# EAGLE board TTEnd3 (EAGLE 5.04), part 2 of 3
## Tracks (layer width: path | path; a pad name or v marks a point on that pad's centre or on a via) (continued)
MASSE  (via drill 0.9 pad 1.5) (continued)
  Oben/V2 2.159: 153.42,152.15 153.42,157.48 153.42,158.75 | 155.96,152.15 155.96,157.48 R318.2 161.04,157.48 161.04,166.37 158.5,168.91 157.23,168.91 | 162.31,147.32 165.61,147.32 | 159.26,147.32 158.5,147.32 158.5,148.08 158.25,148.34 158.25,149.86 155.96,152.15 | 134.37,147.32 131.07,147.32 | 138.18,147.32 136.91,147.32 | 153.42,152.15 153.42,153.42 | 51.82,147.32 53.09,147.32 | 55.63,147.32 58.93,147.32 | 140.72,149.86 143.01,152.15 153.42,152.15 | 153.42,152.15 154.69,152.15 155.96,152.15 | 152.15,208.28 C305.2 | 147.07,208.28 C308.1 | 37.85,208.28 C105.2 | 42.93,208.28 C108.1 | 27.69,147.32 25.15,147.32 | 31.5,147.32 30.23,147.32 | 37.85,160.02 36.58,160.02 | 36.58,160.02 35.31,158.75 | 36.58,158.75 36.58,157.48 | 36.58,157.48 36.58,153.67 | 36.58,149.86 36.58,153.67 | 36.58,158.75 35.31,158.75 | 35.31,158.75 34.04,158.75 | 34.04,158.75 34.04,157.48 | 34.04,157.48 34.04,149.86 | 35.31,158.75 35.31,149.86 | 34.04,157.48 R118.2 28.96,157.48 28.96,166.37 | 35.31,168.91 31.75,168.91 31.5,168.66 29.47,168.66 28.96,168.15 | 28.96,166.37 28.96,168.15 | 28.96,168.15 29.47,167.64 30.23,167.64 | 45.47,161.29 44.2,160.02 42.93,160.02 | 37.85,160.02 42.93,160.02 | 37.85,160.02 36.58,158.75 | 30.23,167.64 28.96,166.37 | 36.58,160.02 35.31,160.02 34.04,158.75 | G117.2 41.91,152.15 38.1,152.15 36.58,153.67 | 40.39,162.56 37.85,160.02 | 40.39,167.64 30.23,167.64 | 36.58,157.48 40.39,157.48 41.66,158.75 | 42.93,160.02 41.66,158.75 | 36.58,158.75 41.66,158.75
  Oben/V2 2.54: 154.69,157.48 155.96,157.48 | 154.69,157.48 153.42,158.75 152.15,160.02 | 154.69,152.15 154.69,157.48
  Oben/V2 2.794: C129.1 51.82,86.36 J103.2 J103.1 46.74,83.82 | G318.2 145.8,147.32 | 145.8,147.32 G317.2 | 150.88,147.32 G309.1 155.96,144.78 158.5,147.32 | 150.88,147.32 G308.1 | 145.8,147.32 138.18,147.32 | 143.26,144.78 140.72,144.78 138.18,147.32 | G118.2 44.2,147.32 | G117.2 44.2,147.32 | 44.2,147.32 51.82,147.32 | 51.82,147.32 49.28,144.78 46.74,144.78 G118.2 | G117.2 49.28,149.86 51.82,147.32 | 143.26,91.44 143.26,83.82 | C318.2 148.34,86.36 J301.1 143.26,83.82 | C330.1 138.18,86.36 J303.1 J303.2 143.26,83.82 | C316.2 143.26,116.84 C328.1 | 143.26,83.82 J301.2 | G317.2 140.72,149.86 138.18,147.32 | 148.34,149.86 MP5.1 150.88,147.32 | 150.88,147.32 158.5,147.32 | G308.1 155.96,149.86 158.5,147.32 | G317.2 G308.1 | 37.85,180.34 37.85,173.99 | 37.85,180.34 38.1,180.59 38.1,187.96 35.06,191.01 35.06,200.41 37.85,203.2 37.85,208.28 37.85,213.36 40.39,215.9 40.39,219.2 40.64,219.46 40.64,222.76 40.39,223.01 40.39,226.06 50.55,236.22 81.03,236.22 82.3,237.49 92.46,237.49 | 40.64,178.82 40.64,189.23 37.6,192.28 37.6,199.14 40.39,201.93 40.39,212.09 42.93,214.63 42.93,224.79 51.82,233.68 82.3,233.68 83.57,234.95 93.73,234.95 | 92.46,232.41 89.92,232.41 | 89.92,232.41 84.84,232.41 83.57,231.14 53.09,231.14 45.47,223.52 45.47,223.01 45.22,222.76 45.22,219.2 45.47,218.95 45.47,213.36 42.93,210.82 42.93,208.28 42.93,200.66 40.14,197.87 40.14,193.29 43.18,190.25 43.18,177.55 42.93,177.29 42.93,173.99 40.39,173.99 | 95,229.87 J2.2 | 100.08,232.41 105.16,232.41 106.43,231.14 139.45,231.14 144.53,226.06 144.53,223.27 144.78,223.01 144.78,219.2 144.53,218.95 144.53,213.36 147.07,210.82 147.07,208.28 147.07,200.66 149.86,197.87 149.86,193.04 146.56,189.74 146.56,179.32 147.07,178.82 147.07,173.99 149.61,173.99
  Oben/V2 2.794: 100.08,232.41 97.54,232.41 | 93.73,234.95 95,234.95 | 95,234.95 95,231.14 | 95,234.95 106.43,234.95 | 93.73,234.95 92.46,236.22 92.46,237.49 | 92.46,237.49 106.43,237.49 107.7,236.22 141.99,236.22 149.61,228.6 149.61,222.76 149.36,222.5 149.36,219.46 149.61,219.2 149.61,215.9 152.15,213.36 152.15,208.28 152.15,203.2 154.94,200.41 154.94,190.5 151.64,187.2 151.64,180.59 154.69,177.55 154.69,173.99 152.15,173.99 | 31.5,147.32 34.04,144.78 G109.1 41.66,144.78 G118.2 | 44.2,147.32 31.5,147.32 | 31.5,147.32 34.04,149.86 35.31,149.86 36.58,149.86 G108.1 G117.2 | 37.85,168.91 35.31,168.91 | 37.85,168.91 40.39,168.91 | 42.93,168.91 40.39,168.91 | 46.74,91.44 46.74,83.82 | 46.74,83.82 J101.2 | 46.74,83.82 J101.1 41.66,86.36 C118.2 | 37.85,173.99 35.31,173.99 35.31,177.8 37.85,180.34 | 105.16,233.68 140.72,233.68 147.07,227.33 147.07,214.63 149.61,212.09 149.61,201.93 152.4,199.14 152.4,191.77 149.1,188.47 149.1,179.58 152.15,176.53 152.15,173.99 | 149.61,173.99 152.15,173.99 | 149.61,173.99 149.61,178.82 | 147.07,168.91 149.61,168.91 | 149.61,168.91 152.15,168.91 | 153.42,168.91 152.15,168.91 | 154.69,168.91 153.42,168.91 | 149.61,168.91 149.61,173.99 | 152.15,168.91 152.15,173.99 | 154.69,168.91 157.23,168.91 | 147.07,168.91 144.53,168.91 144.53,161.29 147.07,161.29 | 147.07,161.29 147.07,168.91 | 149.61,165.1 149.61,168.91 | 149.61,163.83 149.61,165.1 | 149.61,161.29 149.61,163.83 | 149.61,161.29 147.07,161.29 | 149.61,165.1 153.42,168.91 | 149.61,163.83 154.69,168.91 | 147.07,161.29 150.37,157.99 152.91,157.99 | 153.42,157.48 152.91,157.99 | 152.91,157.99 149.61,161.29 | 37.85,173.99 40.39,173.99
  Oben/V2 2.794: 40.39,173.99 40.39,179.07 | 37.85,173.99 37.85,168.91 | 40.39,173.99 40.39,168.91 | 42.93,168.91 45.47,168.91 45.47,161.29 | 42.93,168.91 42.93,161.29 | 40.39,168.91 40.39,167.64 40.39,162.56 40.39,161.29 | 89.92,232.41 92.46,229.87 92.46,223.52 J2.1 97.54,223.52 97.54,229.87 100.08,232.41
  Oben/V2 3.302: C128.1 C129.1 46.74,91.44 | C127.1 C128.1 | C126.1 C127.1 | C126.1 51.82,139.7 46.74,144.78 | C327.1 C328.1 C329.1 | C329.1 C330.1 143.26,91.44 | C317.2 C318.2 143.26,91.44 | C317.2 C316.2 C315.2 | 143.26,104.14 143.26,91.44 | 143.26,104.14 143.26,116.84 143.26,129.54 | 143.26,104.14 C317.2 | C329.1 143.26,104.14 | 143.26,129.54 C315.2 | C327.1 143.26,129.54 | C315.2 148.34,139.7 153.42,144.78 G309.1 | C327.1 138.18,139.7 143.26,144.78 G318.2 | 92.46,232.41 95,229.87 97.54,232.41 | 41.66,144.78 v46.74,139.7 46.74,129.54 | 46.74,129.54 46.74,116.84 | 46.74,116.84 46.74,104.14 | 46.74,104.14 46.74,91.44 | C117.2 C118.2 46.74,91.44 | C116.2 C117.2 | C115.2 C116.2 | C115.2 41.66,139.7 37.85,143.51 G109.1 | 46.74,129.54 C115.2 | 46.74,129.54 C126.1 | 46.74,116.84 C116.2 | 46.74,116.84 C127.1 | 46.74,104.14 C117.2 | 46.74,104.14 C128.1 | 91.19,218.95 95,222.76 J2.1 J2.2 | 143.26,129.54 v143.26,139.7 148.34,144.78 MP5.1 | 92.46,223.52 91.19,222.25 91.19,218.95 | 91.19,218.95 91.19,210.82 92.46,209.55 95,209.55
  Unten/V1 1.016: 72.14,26.67 IC105.3 | IC104.3 R199.1 | 135.64,177.8 C311.1 R330.1 | 163.58,154.94 166.12,157.48 | C111.1 56.9,181.61 58.17,182.88 59.44,182.88 R130.1 | 26.42,154.94 23.88,157.48 | IC101.2 18.8,172.72 | C319.1 150.88,35.56 R371.2 | 171.2,175.26 173.74,177.8 | IC301.2 171.2,170.18 | C132.2 95,182.88 C332.2
  Unten/V1 1.524: G137.1 R233.2 77.22,13.97 75.95,12.7 68.33,12.7 65.79,15.24 56.9,15.24 | 46.74,83.82 46.74,40.64 | R195.1 53.09,33.02 51.82,34.29 51.82,39.37 50.55,40.64 46.74,40.64 | 46.74,40.64 42.93,40.64 41.66,39.37 R177.1 C119.1 R169.2 | R189.1 MP13.1 | R189.1 MP13.1 | C120.2 IC103.2 | 46.74,40.64 R189.1 | 131.07,147.32 C314.1 | 135.64,177.8 135.64,173.99 136.91,172.72 139.45,172.72 140.72,173.99 143.26,173.99 144.53,172.72 144.53,170.18 140.72,166.37 140.72,165.1 | 140.72,165.1 V311.1 C310.1 G317.2 | 140.72,165.1 R323.1 | 166.12,157.48 166.12,163.83 168.66,166.37 IC301.2 | 163.58,154.94 C307.2 161.04,153.67 159.77,152.4 155.96,152.4 | R314.2 C301.2 R305.2 173.74,177.8 | 165.61,147.32 C304.2 | 58.93,147.32 C114.1 | 23.88,157.48 IC101.2 | 26.42,154.94 C107.2 28.96,153.67 32.77,149.86 | R114.2 C101.2 R105.2 18.8,172.72 | 24.39,147.32 C104.2 | G117.2 C110.1 V111.1 R123.1 49.28,168.91 51.82,171.45 51.82,173.99 54.36,176.53 54.36,179.07 55.63,180.34 C111.1 | 42.93,173.99 C109.1 | 35.31,173.99 C106.2 | 143.26,83.82 143.26,53.34 145.8,50.8 145.8,46.99 143.26,44.45 143.26,40.64 | C319.1 R377.1 148.34,39.37 147.07,40.64 143.26,40.64 | 143.26,40.64 138.18,40.64 135.64,38.1 R393.1 | 124.21,17.78 124.21,16.51 125.48,15.24 133.1,15.24 | 124.21,17.78 124.21,22.86 | 124.21,22.86 130.56,22.86 | 143.26,40.64 R389.1 | R389.1 MP14.1 | R376.2 158.5,15.24 IC303.2 153.42,13.97 152.15,12.7 C320.2 148.34,10.16 145.8,10.16 | 124.21,22.86 119.38,22.86 115.32,26.92 IC305.3 | J107.4 J107.3 J107.2 J107.5 84.84,2.54 82.3,5.08 45.47,5.08 44.2,6.35 R190.2 44.2,10.16 | J307.5 J307.2 J307.3 J307.4 105.16,2.54 107.7,5.08 144.53,5.08 145.8,6.35 R390.2 145.8,10.16
  Unten/V1 1.524: 95,203.2 95,208.28 G320.1 G120.1 | 95,203.2 95,200.66 | 34.04,157.48 R118.2 | 95,200.66 95,193.04 | 95,187.96 95,193.04 | v95,162.56 95,182.88 95,187.96 | 41.66,144.78 MP3.1 | 148.34,144.78 MP5.1 | R430.2 G337.1 124.21,17.78 | J101.1 36.58,81.28 v36.58,71.12 | R165.2 R166.2 | R227.1 R226.1 68.33,48.26 69.6,49.53 v69.6,63.5 | v56.9,71.12 56.9,81.28 J103.2 | R184.1 R183.1 44.2,53.34 C121.1 | R189.1 MP13.1 | R176.2 34.04,12.7 C120.2 | R199.1 70.87,25.4 72.14,26.67 | 103.89,145.54 103.89,144.78 J306.1 | R384.1 R383.1 138.18,53.34 139.45,54.61 C321.1 | R389.1 MP14.1 | R366.2 R365.2 164.85,48.26 166.12,49.53 v166.12,63.5 | J301.1 153.42,81.28 v153.42,71.12 | R426.1 R427.1 | 91.19,144.78 J106.1 | v133.1,63.5 133.1,81.28 J303.1 | 171.2,170.18 171.2,175.26 | 145.8,10.16 144.53,10.16 143.26,11.43 R389.1 | 44.2,10.16 45.47,10.16 46.74,11.43 R189.1 | 44.2,10.16 41.66,10.16 C120.2 | 56.9,15.24 IC104.3 | 95,187.96 G122.1 | 95,193.04 V119.3 | 95,203.2 V116.3 | 95,200.66 R136.2 | 95,187.96 G322.1 | 95,187.96 95,190.5 V319.3 | 95,200.66 R336.2 | 95,203.2 V316.3 | MP13.1 54.36,12.7 56.9,15.24 | MP14.1 135.64,12.7 133.1,15.24 | 130.56,22.86 R401.1 | 130.56,22.86 133.1,22.86 | 133.1,15.24 IC304.3
  Unten/V1 1.778: 136.91,147.32 134.37,147.32 | 159.77,147.32 162.31,147.32 | 30.23,147.32 27.69,147.32 | 51.82,147.32 55.63,147.32 | 147.07,172.72 C309.1 147.07,168.91 | 154.69,172.72 C306.2 154.69,168.91 | C106.2 35.31,168.91 | 42.93,168.91 C109.1
  Unten/V1 2.159: 144.53,160.02 143.26,158.75 143.26,154.69 | 143.26,154.69 143.26,153.67 144.53,152.4 148.34,152.4 | 150.88,147.32 G308.1 | 153.42,152.4 154.69,152.4 | 148.34,152.4 153.42,152.4 | 143.26,147.32 138.18,147.32 136.91,147.32 | 134.37,147.32 131.07,147.32 | 158.5,147.32 159.77,147.32 | 162.31,147.32 165.61,147.32 | 153.42,158.75 153.42,160.02 | 153.42,152.4 153.42,157.48 | 153.42,157.48 153.42,158.75 | 27.69,147.32 24.39,147.32 | 31.5,147.32 30.23,147.32 | 55.63,147.32 58.93,147.32 | 41.66,154.94 41.66,152.4 | 41.66,157.48 41.66,154.94 | 41.66,158.75 41.66,157.48 | 41.66,158.75 41.66,160.02 37.85,160.02 | 36.58,152.4 41.66,152.4 | 34.04,149.86 34.04,157.48 34.04,158.75 35.31,160.02 | 37.85,160.02 35.31,160.02 | 37.85,160.02 36.58,158.75 | 36.58,157.48 36.58,152.4 | 36.58,158.75 36.58,157.48 | 41.66,152.4 G117.2 | 36.58,149.86 36.58,152.4 | 35.31,160.02 35.31,149.86 | 153.42,158.75 152.15,160.02 | 149.61,160.02 152.15,160.02 | 148.34,160.02 149.61,160.02 | 148.34,160.02 144.53,160.02 | C105.2 37.85,208.28 | C108.1 42.93,208.28 | 96.27,229.87 J2.2 93.73,229.87 91.19,232.41 | C308.1 147.07,208.28 | C305.2 152.15,208.28 | 155.96,157.48 R318.2 | 158.25,147.57 158.25,151.38 155.96,153.67 | 152.15,160.02 149.61,162.56 | 144.53,160.02 144.53,161.29 | 41.66,157.48 36.58,157.48 | 36.58,158.75 41.66,158.75 | 45.47,161.29 45.47,160.02 46.74,158.75 46.74,156.21 45.47,154.94 | 45.47,154.94 42.93,152.4 41.66,152.4 | 40.39,162.56 37.85,160.02 | 41.66,154.94 45.47,154.94 | 44.2,161.29 41.66,158.75 | 153.42,157.48 152.15,157.48 | 152.15,157.48 149.61,160.02 | 148.34,154.69 148.34,157.48 | 148.34,157.48 148.34,160.02 | 148.34,152.4 148.34,154.69 | 148.34,154.69 143.26,154.69
  Unten/V1 2.159: 148.34,157.48 152.15,157.48
  Unten/V1 2.54: 154.69,160.02 153.42,160.02 | 154.69,160.02 155.96,158.75 155.96,157.48 155.71,157.23 155.71,154.69 | G308.1 155.71,154.69 | 154.69,152.4 154.69,160.02 | 155.71,154.69 155.71,152.65 155.96,152.4 | 42.93,210.82 45.47,213.36 45.47,219.2 arc-90 45.22,219.46 45.22,222.5 arc90 45.47,222.76 45.47,223.52 | 37.85,208.28 37.85,213.36 40.39,215.9 | 103.89,145.54 103.89,146.05 107.7,149.86 T2.11 107.7,157.48 102.62,162.56 v95,162.56 89.92,157.48 T1.11 91.19,153.67 91.19,144.78
  Unten/V1 2.794: C129.1 51.82,86.36 J103.2 J103.1 J101.2 | C118.2 41.66,86.36 J101.1 J101.2 | 46.74,83.82 J101.2 | 150.88,147.32 G309.1 148.34,144.78 G318.2 | 150.88,147.32 158.5,147.32 | 153.42,144.78 155.96,144.78 158.5,147.32 | 150.88,147.32 143.26,147.32 | 150.88,147.32 153.42,147.32 | G108.1 39.12,147.32 | 39.12,147.32 G109.1 41.66,144.78 | 36.58,144.78 34.04,144.78 31.5,147.32 | 51.82,147.32 49.28,144.78 46.74,144.78 G118.2 | G117.2 44.2,147.32 | G118.2 44.2,147.32 | G108.1 36.58,149.86 35.31,149.86 34.04,149.86 32.77,149.86 32.77,148.59 31.5,147.32 | 44.2,147.32 51.82,147.32 | 39.12,147.32 31.5,147.32 | C330.1 138.18,86.36 J303.1 J303.2 143.26,83.82 | C318.2 148.34,86.36 J301.1 143.26,83.82 | 143.26,83.82 J301.2 | 143.26,144.78 G318.2 | 41.66,144.78 G118.2 | 41.66,152.4 41.66,144.78 | G108.1 G117.2 | 51.82,147.32 49.28,149.86 G117.2 | G317.2 148.34,149.86 | 148.34,149.86 G308.1 155.96,149.86 | G317.2 140.72,149.86 | 140.72,149.86 138.18,147.32 140.72,144.78 G318.2 | G318.2 G317.2 | 158.5,147.32 158.25,147.57 155.96,149.86 | 148.34,149.86 148.34,152.4 143.26,152.4 140.72,149.86 | 155.96,149.86 155.96,152.4 | 42.93,210.82 42.93,208.28 42.93,200.66 40.14,197.87 40.14,193.29 43.18,190.25 43.18,174.24 42.93,173.99 40.39,173.99 | 40.39,215.9 40.39,218.95 40.64,219.2 40.64,222.76 40.39,223.01 40.39,226.06 50.55,236.22 53.09,236.22 | 93.73,229.87 93.73,232.41 | 93.73,232.41 92.46,233.68 v93.73,233.68 53.09,233.68 | 53.09,231.14 45.47,223.52 | 53.09,236.22 53.09,233.68 | 53.09,233.68 53.09,231.14 | 53.09,236.22 v93.73,236.22 96.27,233.68 96.27,229.87 | 53.09,236.22 54.36,236.22 42.93,224.79 42.93,214.63 40.39,212.09 40.39,201.93 37.6,199.14 37.6,192.02 40.64,188.98 40.64,174.24 40.39,173.99
  Unten/V1 2.794: 53.09,231.14 83.57,231.14 84.84,232.41 91.19,232.41 93.73,232.41 | 144.53,233.68 149.61,228.6 149.61,222.76 arc90 149.36,222.5 149.36,219.46 arc-90 149.61,219.2 149.61,215.9 152.15,213.36 152.15,208.28 149.61,208.28 | 140.72,233.68 v107.7,233.68 | 140.72,233.68 144.53,233.68 | v107.7,233.68 v107.7,231.14 139.45,231.14 144.53,226.06 144.53,223.01 arc90 144.78,222.76 144.78,219.2 arc90 144.53,218.95 144.53,213.36 147.07,210.82 147.07,208.28 149.61,208.28 | 140.72,233.68 147.07,227.33 147.07,214.63 149.61,212.09 149.61,208.28 | v107.7,233.68 v110.24,236.22 141.99,236.22 144.53,233.68 | 144.53,165.1 148.34,168.91 149.61,168.91 | 149.61,192.79 149.86,193.04 149.86,198.12 | 152.15,179.07 151.64,179.58 151.64,187.45 152.15,187.96 | 37.85,173.99 35.31,173.99 35.31,177.8 37.85,180.34 | 40.39,173.99 37.85,173.99 | 37.85,173.99 37.85,180.34 | 37.85,180.34 38.1,180.59 38.1,187.71 35.06,190.75 35.06,200.41 37.85,203.2 37.85,208.28 | 37.85,168.91 36.58,168.91 | 36.58,168.91 35.31,168.91 | 40.39,168.91 37.85,168.91 | 40.39,168.91 42.93,168.91 | 37.85,173.99 37.85,168.91 | 40.39,173.99 40.39,168.91 | 42.93,168.91 45.47,168.91 45.47,161.29 44.2,161.29 42.93,161.29 | 42.93,168.91 42.93,161.29 | 40.39,168.91 40.39,165.1 | 40.39,165.1 40.39,162.56 40.39,161.29 42.93,161.29 | 40.39,165.1 36.58,168.91 | 149.61,168.91 152.15,168.91 | 152.15,168.91 154.69,168.91 153.42,167.64 | 152.15,173.99 154.69,173.99 | 152.15,173.99 149.61,173.99 | 149.61,173.99 147.58,173.99 | 149.61,168.91 149.61,173.99 | 152.15,168.91 152.15,173.99
  Unten/V1 3.302: C126.1 51.82,139.7 46.74,144.78 | C126.1 C127.1 | C127.1 C128.1 | C128.1 C129.1 46.74,91.44 | C117.2 C118.2 46.74,91.44 | C116.2 C117.2 | C115.2 C116.2 | 46.74,129.54 C126.1 | 46.74,129.54 C115.2 | 46.74,116.84 C116.2 | 46.74,116.84 C127.1 | 46.74,104.14 C128.1 | 46.74,104.14 C117.2 | 46.74,91.44 46.74,83.82 | 46.74,104.14 46.74,91.44 | 46.74,116.84 46.74,104.14 | 46.74,129.54 46.74,116.84 | C327.1 143.26,129.54 | 143.26,129.54 C315.2 | 143.26,116.84 C316.2 | C328.1 143.26,116.84 | C329.1 143.26,104.14 | 143.26,104.14 C317.2 | 143.26,91.44 C318.2 C317.2 | 143.26,91.44 C330.1 C329.1 | C316.2 C317.2 | C316.2 C315.2 | C328.1 C329.1 | C328.1 C327.1 | 143.26,91.44 143.26,83.82 | 143.26,104.14 143.26,91.44 | 143.26,116.84 143.26,104.14 | 143.26,116.84 143.26,129.54 | 143.26,129.54 v143.26,139.7 148.34,144.78 | C115.2 41.66,139.7 36.58,144.78 G109.1 | 143.26,144.78 138.18,139.7 C327.1 | C315.2 148.34,139.7 153.42,144.78 G309.1 | 46.74,129.54 v46.74,139.7 41.66,144.78 | 144.53,161.29 144.53,165.1 | 148.34,174.75 147.07,176.02 147.07,190.25 149.61,192.79 149.61,177.8 152.15,175.26 | 147.07,161.29 147.07,163.83 149.61,166.37 | 149.61,163.83 149.61,166.37 | 149.61,163.83 149.61,162.56 149.61,161.29 | 149.61,166.37 152.15,168.91 | 154.69,173.99 154.69,176.53 152.15,179.07 | 149.61,163.83 153.42,167.64 | 149.86,198.12 147.07,200.91 147.07,208.28 | 152.15,203.2 154.69,200.66 154.69,190.5 152.15,187.96 152.15,199.39 | 152.15,208.28 152.15,203.2 | 152.15,199.39 149.61,201.93 149.61,208.28 | 152.15,199.39 152.15,203.2
N$1
  Oben/V2 1.016: C120.1 41.66,10.16 C130.1
  Unten/V1 1.016: C130.1 R202.2
N$2
  Oben/V2 1.016: C130.2 56.9,15.24 R200.1
  Unten/V1 1.016: IC102.3 50.55,22.86 51.82,21.59 51.82,16.51 C130.2
N$3
  Oben/V2 1.016: R176.1 IC103.1
  Unten/V1 1.016: R175.2 30.23,20.32 32.77,17.78 R176.1
N$4
  Oben/V2 1.016: IC103.3 36.58,6.35 37.85,5.08 75.95,5.08 79.76,8.89 G138.1
  Unten/V1 1.016: IC103.3 36.58,20.32 | MP11.1 R174.2 R175.1 36.58,20.32 | 36.58,20.32 V128.2
N$5
  Unten/V1 1.016: V128.1 IC102.7
N$6
  Oben/V2 1.016: IC104.1 56.9,17.78 R198.1
  Unten/V1 1.016: R198.1 R199.2
N$7
  Oben/V2 1.016: R192.1 54.36,25.4 V130.2 | R198.2 59.44,24.13 60.71,22.86 65.79,22.86 67.06,21.59 | MP12.1 81.03,25.4 78.49,22.86 68.33,22.86 67.06,21.59 | 67.06,21.59 G135.2
  Unten/V1 1.016: IC104.2 V130.2 R198.2
N$8
  Unten/V1 1.016: IC102.4 50.55,25.4 53.09,22.86 V130.1
N$9
  Unten/V1 1.016: C125.1 44.2,21.59 42.93,22.86 | 42.93,22.86 IC102.6 | 42.93,22.86 44.2,24.13 R188.1 C124.1 42.93,30.48 41.66,31.75 R177.2 | R186.1 42.93,35.56 41.66,34.29 R177.2 | R177.2 C119.2
N$10
  Oben/V2 1.016: R187.1 48.01,33.02 46.74,31.75 46.74,21.59 48.01,20.32 | R190.1 46.74,15.24 | 48.01,20.32 IC102.2 | 48.01,20.32 46.74,19.05 46.74,15.24 | 46.74,15.24 C125.2
N$11
  Oben/V2 1.016: R187.2 45.47,33.02 46.74,34.29 46.74,36.83 45.47,38.1 R185.2 C122.2
N$12
  Unten/V1 1.016: V308.2 176.28,167.64 176.28,158.75 177.55,157.48 | 177.55,157.48 R310.1 | 177.55,157.48 176.28,156.21 G306.2
N$13
  Unten/V1 1.016: V128.3 39.12,25.4 39.12,26.67 37.85,27.94 R173.2
N$14
  Unten/V1 1.016: R196.1 53.09,30.48 51.82,29.21 51.82,26.67 53.09,25.4 V130.3
N$15
  Oben/V2 1.016: R170.2 35.31,35.56 34.04,34.29 34.04,31.75 32.77,30.48 R172.2
  Unten/V1 1.016: R172.2 30.23,30.48 23.88,36.83 23.88,39.37 22.61,40.64 V123.3
N$16  (via drill 0.9 pad 1.5)
  Oben/V2 1.016: v44.2,48.26 R184.2
  Unten/V1 1.016: R191.2 51.82,55.88 51.82,54.61 | 51.82,54.61 R183.2 R184.2 54.36,48.26 56.9,50.8 V129.2 | R168.2 36.58,55.88 V127.2 36.58,49.53 40.39,45.72 42.93,45.72 44.2,46.99 v44.2,48.26 | 51.82,54.61 C121.2
N$17
  Oben/V2 0.762: V126.3 26.72,35.87 26.42,35.56 28.96,33.02 R171.2
N$18
  Oben/V2 1.016: 51.82,60.96 51.82,68.58 R178.2 | R181.2 51.82,60.96 | V137.2 74.68,38.1 79.76,43.18 79.76,49.53 73.41,55.88 V136.1 69.6,58.42 60.71,58.42 59.44,57.15 | 59.44,57.15 V129.1 | 59.44,57.15 55.63,60.96 51.82,60.96
N$19
  Oben/V2 0.762: V126.2 26.42,38.1 25.15,38.1
  Oben/V2 1.016: 25.15,38.1 22.61,35.56 V123.1
  Unten/V1 1.016: R173.1 30.23,27.94 22.61,35.56 V123.1
N$20
  Oben/V2 0.762: V126.1 28.66,37.8 28.96,38.1 R169.1
N$21
  Oben/V2 0.762: V126.4 28.63,35.89 28.96,35.56 R170.1
N$22
  Oben/V2 0.762: V133.3 66.75,35.26 67.06,35.56 64.52,38.1 R193.1
N$23
  Oben/V2 1.524: 6.1,101.6 6.1,102.87 8.64,105.41 18.8,105.41 20.07,104.14 G125.2 20.07,99.06 17.53,96.52 V121.1 | 6.1,101.6 2.29,97.79 2.29,95.25 3.56,93.98 3.56,66.04 G126.1 | 6.1,101.6 V120.1
  Unten/V1 1.524: 25.15,53.34 23.88,52.07 23.88,49.53 22.61,48.26 R165.1 | 11.18,58.42 G126.1 | 11.18,58.42 22.61,58.42 23.88,57.15 23.88,54.61 25.15,53.34 | 25.15,53.34 V124.2 | G127.1 11.18,58.42
N$24
  Oben/V2 1.524: G125.1 21.34,90.17 21.34,85.34 22.86,83.82 R162.2
  Unten/V1 1.524: R162.2 26.42,81.28 V124.1
N$25
  Unten/V1 1.016: J107.1 86.11,5.08 83.57,7.62 65.79,7.62 64.52,8.89 64.52,10.16 | R202.1 64.52,10.16 | 64.52,10.16 MP7.1
N$26
  Oben/V2 1.524: R153.1 R152.1 26.42,109.22 26.42,106.68 | R154.1 R153.1 | R155.1 R154.1 | R156.1 R155.1 | R157.1 R156.1 | R158.1 R157.1 | R159.1 R158.1 | R160.1 R159.1 | R160.1 R161.1 26.42,86.36 26.42,88.9 | 26.42,104.14 26.42,106.68 | 26.42,101.6 26.42,104.14 | 26.42,99.06 26.42,101.6 | 26.42,96.52 26.42,99.06 | 26.42,93.98 26.42,96.52 | 26.42,91.44 26.42,93.98 | 26.42,88.9 26.42,91.44 | R160.1 26.42,88.9 | R159.1 26.42,91.44 | R158.1 26.42,93.98 | R157.1 26.42,96.52 | R156.1 26.42,99.06 | R155.1 26.42,101.6 | R154.1 26.42,104.14 | R153.1 26.42,106.68
  Unten/V1 1.524: R153.1 R152.1 | R154.1 R153.1 | R155.1 R154.1 | R161.1 R160.1 | R160.1 R159.1 | R159.1 R158.1 | R158.1 R157.1 | R157.1 R156.1 | R156.1 R155.1 | 22.61,91.44 22.61,88.9 R160.1 | R161.1 20.07,86.36 | R152.1 21.34,109.22 20.07,107.95 | 22.61,101.6 22.61,104.14 R154.1 | 21.34,99.06 22.61,100.33 22.61,101.6 | 21.34,96.52 21.34,99.06 | 22.61,91.44 22.61,93.98 | 21.34,96.52 21.34,93.98 | R153.1 20.07,106.68 | R155.1 22.61,101.6 | R156.1 21.34,99.06 | R157.1 21.34,96.52 | R158.1 22.61,93.98 | R159.1 22.61,91.44 | R161.1 22.61,86.36 21.34,85.09 21.34,69.85 22.61,68.58 R163.2 R164.1 | 16.26,92.71 17.53,92.71 18.8,93.98 21.34,93.98 | 22.61,93.98 21.34,93.98 | R152.1 26.42,109.22 26.42,106.68 | 26.42,104.14 26.42,106.68 | 26.42,101.6 26.42,104.14 | 26.42,99.06 26.42,101.6 | 26.42,96.52 26.42,99.06 | 26.42,93.98 26.42,96.52 | 26.42,91.44 26.42,93.98 | 26.42,88.9 26.42,91.44 | 26.42,88.9 26.42,86.36 R161.1 | R160.1 26.42,88.9 | R159.1 26.42,91.44 | R158.1 26.42,93.98 | R157.1 26.42,96.52 | R156.1 26.42,99.06 | R155.1 26.42,101.6 | R154.1 26.42,104.14 | R153.1 26.42,106.68
  Unten/V1 2.794: 6.1,95.25 6.1,96.52 V121.3 | 8.64,92.71 6.1,95.25 | 12.45,92.71 16.26,92.71 16.26,85.09 | 12.45,92.71 8.64,92.71 | 8.64,85.09 6.1,85.09 4.83,86.36 4.83,96.52 | 12.45,85.09 8.64,85.09 | 16.26,85.09 12.45,85.09 | 16.26,85.09 18.8,85.09 20.07,86.36 22.61,88.9 21.34,87.63 18.8,87.63 17.53,88.9 8.64,88.9 | 20.07,107.95 20.07,106.68 22.61,104.14 | 8.64,88.9 7.37,88.9 6.1,90.17 6.1,95.25 | 8.64,88.9 8.64,92.71 | 8.64,85.09 8.64,88.9 | 12.45,85.09 12.45,92.71
N$27
  Oben/V2 0.762: V133.2 67.06,33.02 67.06,32.51 66.3,31.75 65.79,31.75 64.52,30.48
  Oben/V2 1.016: R196.2 64.52,30.48
  Unten/V1 1.016: R196.2 63.25,30.48 64.52,31.75 64.52,34.29 70.87,40.64 V137.1
N$28
  Oben/V2 0.762: V133.1 64.83,33.33 64.52,33.02 R195.2
N$29  (via drill 3.2 pad 5.99)
  other vias: 11.18,247.65
N$30
  Oben/V2 0.762: V133.4 64.83,35.26 64.52,35.56 R194.1
N$31
  Oben/V2 1.016: R194.2 58.17,35.56 59.44,34.29 59.44,30.48 R197.1
  Unten/V1 1.016: V137.3 72.14,34.29 70.87,33.02 68.33,33.02 63.25,27.94 R197.1
N$32
  Unten/V1 1.016: V125.3 R163.1
N$33
  Unten/V1 1.016: G127.2 R166.1 23.88,45.72 26.42,48.26 V124.3 V125.1
N$34  (via drill 3.2 pad 5.99)
  other vias: 82.3,69.85
N$35
  Oben/V2 1.524: R214.1 R213.1 72.14,109.22 73.41,107.95 | R215.1 R214.1 | R216.1 R215.1 | R217.1 R216.1 | R218.1 R217.1 | R219.1 R218.1 | R220.1 R219.1 | R220.1 R221.1 R222.1 | R214.1 73.41,106.68 | R215.1 72.14,104.14 73.41,105.41 70.87,102.87 70.87,101.6 | R216.1 70.87,101.6 | R217.1 72.14,99.06 73.41,97.79 70.87,100.33 70.87,101.6 | R218.1 73.41,96.52 | R219.1 72.14,93.98 | 72.14,93.98 74.68,96.52 | R220.1 72.14,93.98
  Oben/V2 2.794: 73.41,107.95 73.41,106.68 73.41,105.41 | 73.41,96.52 73.41,97.79 75.95,97.79 77.22,96.52 74.68,96.52 73.41,96.52
  Unten/V1 1.524: R222.1 R221.1 | R221.1 R220.1 | R220.1 R219.1 | R219.1 R218.1 | R218.1 R217.1 | R217.1 R216.1 | R216.1 R215.1 | R215.1 R214.1 | R214.1 R213.1 | 73.41,97.79 72.14,99.06 | 72.14,99.06 70.87,100.33 70.87,101.6 | 70.87,101.6 70.87,104.14 R215.1 | R213.1 72.14,109.22 73.41,107.95 | R214.1 73.41,106.68 | 70.87,93.98 73.41,93.98 73.41,96.52 R218.1 | 70.87,91.44 70.87,93.98 | 70.87,91.44 70.87,88.9 R221.1 | R220.1 70.87,91.44 | R219.1 70.87,93.98 | 70.87,93.98 77.22,93.98 | R222.1 72.14,86.36 73.41,87.63 | R216.1 70.87,101.6 | R217.1 72.14,99.06 | R213.1 67.06,109.22 67.06,106.68 | 67.06,104.14 67.06,106.68 | 67.06,101.6 67.06,104.14 | 67.06,99.06 67.06,101.6 | 67.06,96.52 67.06,99.06 | 67.06,93.98 67.06,96.52 | 67.06,91.44 67.06,93.98 | 67.06,88.9 67.06,91.44 | 67.06,88.9 67.06,86.36 R222.1 | R221.1 67.06,88.9 | R220.1 67.06,91.44 | R219.1 67.06,93.98 | R218.1 67.06,96.52 | R217.1 67.06,99.06 | R216.1 67.06,101.6 | R215.1 67.06,104.14 | R214.1 67.06,106.68 | R225.2 R224.2 70.87,68.58 72.14,69.85 72.14,85.09 70.87,86.36 R222.1
  Unten/V1 2.794: 77.22,96.52 75.95,97.79 73.41,97.79 73.41,96.52 V135.3 77.22,96.52 | 70.87,104.14 73.41,106.68 73.41,107.95 | 70.87,88.9 72.14,87.63 73.41,87.63 74.68,87.63 77.22,90.17 77.22,93.98 77.22,96.52
N$36
  Oben/V2 1.524: R223.1 70.62,83.82 72.14,85.34 72.14,90.17 G130.2
  Unten/V1 1.524: R223.1 67.06,81.28 V132.1
N$37
  Oben/V2 1.524: V135.1 87.38,96.52 91.19,100.33 91.19,104.14 89.92,105.41 81.03,105.41 77.22,101.6 V134.1 | V132.2 68.33,53.34 69.6,52.07 69.6,49.53 70.87,48.26 R226.2
  Unten/V1 1.524: V135.1 87.38,96.52 87.38,63.5 G133.2 79.76,55.88 79.76,48.26 | V134.1 G130.1 | R226.2 79.76,48.26 | 79.76,48.26 G134.2
N$38
  Unten/V1 1.524: G132.1 G133.1 74.68,54.61 73.41,53.34 V136.2
N$39
  Unten/V1 1.524: G132.2 R225.1
N$40
  Unten/V1 1.016: V131.3 R224.1
N$41
  Oben/V2 1.016: V132.3 67.06,48.26 69.6,45.72 R227.2
  Oben/V2 1.524: R227.2 G134.1
  Unten/V1 1.524: V131.1 V132.3
N$42
  Unten/V1 1.016: V122.3 20.07,55.88 16.26,52.07 16.26,44.45 17.53,43.18 R167.1
N$43
  Oben/V2 1.016: R230.2 69.6,11.43 63.25,17.78 R201.2
  Unten/V1 1.016: R201.2 63.25,17.78 64.52,19.05 64.52,21.59 65.79,22.86 73.41,22.86 77.22,26.67 IC105.1 C131.2 | R230.2 R231.2
N$44
  Unten/V1 1.016: R229.1 C131.1 73.41,30.48 74.68,29.21 IC105.2
N$45
  Unten/V1 1.016: IC105.5 G137.2 R230.1
N$46
  Oben/V2 1.016: R231.1 72.14,13.97 74.68,11.43 R232.2
  Unten/V1 1.016: R231.1 IC105.6 | R232.2 R233.1
N$47
  Oben/V2 1.016: G136.1 82.3,29.21 78.49,25.4 70.87,25.4 69.6,26.67 IC105.4
  Unten/V1 1.016: G135.1 IC105.4
N$48  (via drill 3.2 pad 5.99)
  other vias: 31.5,247.65
N$49  (via drill 3.2 pad 5.99)
  other vias: 54.36,247.65
N$50
  Oben/V2 1.524: R143.2 R142.2 21.34,134.62 20.07,133.35 | R144.1 R143.2 | R145.2 R144.1 | R146.2 R145.2 | R147.1 R146.2 | R148.1 R147.1 | R148.1 R149.1 | R150.2 R149.1 | R150.2 R151.1 21.34,111.76 20.07,113.03 | R143.2 20.07,132.08 | R144.1 20.07,129.54 | R145.2 20.07,127 | R146.2 20.07,124.46 | R147.1 20.07,121.92 | R148.1 20.07,119.38 | R149.1 20.07,116.84 | R150.2 20.07,114.3
  Oben/V2 2.794: 20.07,113.03 20.07,114.3 20.07,116.84 20.07,119.38 20.07,121.92 20.07,124.46 20.07,127 20.07,129.54 20.07,132.08 20.07,133.35
  Unten/V1 1.524: R143.2 R142.2 21.34,134.62 20.07,133.35 | R144.1 R143.2 | R145.2 R144.1 | R146.2 R145.2 | R147.1 R146.2 | R148.1 R147.1 | R148.1 R149.1 | R150.2 R149.1 | R150.2 R151.1 20.07,111.76 | 16.26,129.54 16.26,132.08 | 16.26,127 16.26,129.54 | 16.26,127 16.26,124.46 20.07,124.46 R146.2 | 20.07,132.08 R143.2 | R144.1 20.07,129.54 16.26,129.54 | R145.2 20.07,127 16.26,127 | R147.1 20.07,121.92 16.26,121.92 | R148.1 20.07,119.38 16.26,119.38 | R149.1 20.07,116.84 16.26,116.84 | R150.2 20.07,114.3 16.26,114.3
  Unten/V1 2.794: 16.26,132.08 17.53,133.35 20.07,133.35 20.07,132.08 20.07,129.54 20.07,127 20.07,124.46 20.07,121.92 20.07,119.38 20.07,116.84 20.07,114.3 20.07,111.76 18.8,111.76 16.26,109.22 16.26,102.87 | 16.26,119.38 16.26,121.92 16.26,124.46 11.18,119.38 11.18,114.3 | 16.26,102.87 16.26,101.6 V120.3 | 16.26,102.87 13.72,105.41 | 11.18,114.3 11.18,107.95 13.72,105.41 | 16.26,119.38 16.26,116.84 16.26,114.3 13.72,111.76 13.72,105.41 | 11.18,114.3 16.26,119.38
N$51
  Oben/V2 1.524: R204.1 R203.1 72.14,134.62 73.41,133.35 | R205.1 R204.1 | R206.2 R205.1 | R207.1 R206.2 | R208.2 R207.1 | R209.1 R208.2 | R210.2 R209.1 | R211.2 R210.2 | R211.2 R212.2 72.14,111.76 73.41,113.03 | R204.1 73.41,132.08 | R205.1 73.41,129.54 | R206.2 73.41,127 | R207.1 73.41,124.46 | R208.2 73.41,121.92 | R209.1 73.41,119.38 | R210.2 73.41,116.84 | R211.2 73.41,114.3
  Oben/V2 2.794: 73.41,113.03 73.41,114.3 73.41,116.84 73.41,119.38 73.41,121.92 73.41,124.46 73.41,127 73.41,129.54 73.41,132.08 73.41,133.35
  Unten/V1 1.524: R204.1 R203.1 72.14,134.62 73.41,133.35 | R205.1 R204.1 | R206.2 R205.1 | R207.1 R206.2 | R208.2 R207.1 | R209.1 R208.2 | R210.2 R209.1 | R211.2 R210.2 | R211.2 R212.2 74.68,111.76 79.76,111.76 | 77.22,129.54 77.22,132.08 73.41,132.08 R204.1 | 77.22,127 77.22,129.54 | 77.22,127 77.22,124.46 73.41,124.46 R207.1 | R211.2 73.41,114.3 77.22,114.3 | R210.2 73.41,116.84 77.22,116.84 | R209.1 73.41,119.38 77.22,119.38 | R208.2 73.41,121.92 77.22,121.92 | R206.2 73.41,127 77.22,127 | R205.1 73.41,129.54 77.22,129.54
  Unten/V1 2.794: 87.38,101.6 87.38,102.87 86.11,104.14 86.11,105.41 | 86.11,105.41 81.03,105.41 74.68,111.76 73.41,113.03 73.41,114.3 73.41,116.84 73.41,119.38 73.41,121.92 73.41,124.46 73.41,127 73.41,129.54 73.41,132.08 73.41,133.35 75.95,133.35 77.22,132.08 | 77.22,119.38 77.22,121.92 77.22,124.46 88.65,113.03 88.65,107.95 | 77.22,119.38 77.22,116.84 77.22,114.3 79.76,111.76 86.11,105.41 | 87.38,101.6 88.65,102.87 88.65,107.95 | 87.38,101.6 V134.3 | 77.22,119.38 88.65,107.95
N$52  (via drill 0.9 pad 1.5)
  Oben/V2 1.016: C122.1 R185.1 | R186.2 50.55,35.56 51.82,34.29 51.82,31.75 50.55,30.48 C124.2 | R167.2 30.23,43.18 35.31,48.26 37.85,48.26 40.39,45.72 46.74,45.72 C122.1 | R229.2 69.6,38.1 R228.1 63.25,43.18 61.98,44.45 61.98,45.72 59.44,48.26 55.63,48.26 50.55,43.18 C122.1
  Oben/V2 1.524: 23.88,74.93 G128.1 | 69.6,74.93 G131.2 | J102.1 46.74,73.66 46.74,52.07 48.01,50.8 v49.28,50.8
  Oben/V2 2.54: 65.79,133.35 65.79,135.89 68.33,138.43 74.68,138.43 77.22,140.97 81.03,140.97 83.57,143.51 83.57,147.32 86.11,149.86 86.11,153.67 82.3,157.48 T1.12
  Oben/V2 2.794: 44.2,74.93 39.12,74.93 | 12.45,93.98 12.45,96.52 | 14.99,91.44 12.45,93.98 | 20.07,77.47 20.07,74.93 | 20.07,77.47 20.07,80.01 | 17.53,88.9 17.53,85.09 20.07,82.55 | 17.53,88.9 14.99,91.44 | 9.91,83.82 7.37,86.36 7.37,91.44 9.91,93.98 | 12.45,81.28 9.91,83.82 | 17.53,76.2 12.45,81.28 | 20.07,74.93 18.8,74.93 17.53,76.2 | 9.91,93.98 9.91,96.52 | 83.57,96.52 83.57,100.33 V134.2 81.03,100.33 81.03,96.52 | 81.03,93.98 81.03,96.52 | 78.49,91.44 75.95,88.9 75.95,85.09 | 78.49,91.44 81.03,93.98 | 73.41,74.93 73.41,78.74 | 73.41,78.74 73.41,82.55 | 73.41,82.55 75.95,85.09 | 73.41,74.93 74.68,74.93 75.95,76.2 | 75.95,76.2 81.03,81.28 | 81.03,81.28 83.57,83.82 | 83.57,83.82 86.11,86.36 86.11,91.44 83.57,93.98 | 83.57,93.98 83.57,96.52 | 83.57,96.52 82.3,95.25 | 44.2,74.93 J102.1 44.2,77.47 | 44.2,74.93 69.6,74.93 70.87,74.93 | 70.87,74.93 72.14,76.2 J104.1 J104.2 50.55,77.47 | 70.87,74.93 73.41,74.93 | 44.2,77.47 50.55,77.47 | 56.9,80.01 56.9,78.74 55.63,77.47 50.55,77.47 | 50.55,77.47 70.87,77.47 | 20.07,74.93 23.88,74.93 39.12,74.93 | 39.12,74.93 J102.2 37.85,77.47 | 26.42,77.47 20.07,77.47 | 37.85,77.47 26.42,77.47 | 37.85,77.47 36.58,78.74 | 36.58,78.74 36.58,80.01 | 36.58,80.01 35.31,81.28 34.04,81.28 32.77,80.01 30.23,80.01 | 20.07,80.01 20.07,82.55 | 20.07,82.55 22.61,80.01 | 22.61,80.01 25.15,80.01 | 25.15,80.01 26.42,81.28 28.96,81.28 30.23,80.01 | 17.53,76.2 17.53,88.9 | 17.53,76.2 14.99,78.74 14.99,91.44 | 12.45,81.28 12.45,93.98 | 9.91,83.82 9.91,93.98 | 56.9,80.01 58.17,81.28 59.44,81.28 60.71,80.01 63.25,80.01 64.52,81.28 65.79,81.28 67.06,81.28 68.33,80.01 70.87,80.01 73.41,82.55 | 75.95,76.2 75.95,85.09 | 75.95,76.2 78.49,78.74 78.49,91.44
  Oben/V2 2.794: 81.03,81.28 81.03,93.98 | 83.57,83.82 83.57,93.98 | 44.2,77.47 37.85,77.47 | 9.91,96.52 9.91,100.33 V120.2 12.45,100.33 12.45,96.52 | 9.91,96.52 V121.2 12.45,96.52 | 81.03,96.52 V135.2 83.57,96.52 | 36.58,78.74 34.04,78.74 32.77,77.47 26.42,77.47 | 25.15,80.01 30.23,80.01 | 20.07,80.01 22.61,80.01 | 56.9,80.01 58.17,78.74 73.41,78.74 | 36.58,80.01 56.9,80.01
  Oben/V2 3.302: 65.79,81.28 65.79,133.35
  Unten/V1 1.016: C124.2 R188.2 | R185.1 R186.2
  Unten/V1 1.524: C122.1 v49.28,50.8
  Unten/V1 2.794: 12.45,97.79 12.45,100.33 V120.2 9.91,100.33 9.91,97.79 V121.2 12.45,97.79 | 83.57,97.79 83.57,100.33 V134.2 81.03,100.33 81.03,97.79 V135.2 83.57,97.79
N$54
  Oben/V2 1.016: R399.1 130.56,16.51 131.83,15.24 C326.2
  Unten/V1 1.016: IC302.3 139.45,20.32 138.18,19.05 138.18,16.51 C326.2
N$55
  Unten/V1 1.016: R375.2 159.77,20.32 157.23,17.78 R376.1 IC303.1
N$56
  Oben/V2 1.016: IC303.3 153.42,12.7 153.42,6.35 152.15,5.08 114.05,5.08 110.24,8.89 G338.1
  Unten/V1 1.016: 155.96,22.86 R375.1 | 155.96,22.86 R374.2 MP9.1 | IC303.3 V328.2 153.42,22.86 155.96,22.86
N$57
  Oben/V2 1.016: V119.2 89.92,193.04 89.92,194.31 88.65,195.58 R138.2 V118.1
N$58
  Unten/V1 1.016: R398.1 R401.2 IC304.1
N$59
  Oben/V2 1.016: IC302.4 139.45,17.78 138.18,19.05 138.18,21.59 136.91,22.86 V330.1
N$60
  Unten/V1 1.016: C325.1 145.8,19.05 147.07,20.32 | 147.07,20.32 IC302.6 | 147.07,20.32 145.8,21.59 R388.1 C324.1 147.07,30.48 148.34,31.75 R377.2 | R377.2 148.34,34.29 147.07,35.56 R386.1 | R377.2 C319.2
N$61
  Oben/V2 1.016: 141.99,22.86 IC302.2 | R387.1 141.99,33.02 143.26,31.75 143.26,24.13 141.99,22.86 | 143.26,15.24 143.26,21.59 141.99,22.86 | 143.26,15.24 R390.1 | C325.2 143.26,15.24
N$62
  Oben/V2 1.016: R387.2 144.53,33.02 143.26,34.29 143.26,36.83 144.53,38.1 R385.2 C322.2
N$63
  Oben/V2 1.016: V328.3 R373.2
N$64
  Unten/V1 1.016: V330.3 R397.1
N$65
  Unten/V1 1.016: V323.3 164.85,35.56 159.77,30.48 R372.2 157.23,30.48 155.96,31.75 155.96,34.29 154.69,35.56 R370.2
N$66
  Oben/V2 1.016: V323.2 171.2,38.1 176.28,43.18 176.28,49.53 169.93,55.88 V322.1 166.12,58.42 159.77,58.42 155.96,54.61 | 155.96,54.61 V327.1 | 155.96,54.61 154.18,56.39 149.1,56.39 147.07,58.42 R382.1
  Unten/V1 1.016: R379.1 148.34,64.77 148.34,59.69 147.07,58.42 R382.1
N$67
  Oben/V2 0.762: R369.2 161.04,38.1 163.58,35.56 163.28,35.26 V326.3
N$68
  Oben/V2 0.762: V326.2 163.58,33.02 163.58,31.75
  Oben/V2 1.016: 163.58,31.75 159.77,27.94 R373.1
  Unten/V1 1.016: V323.1 169.93,40.64 171.2,39.37 171.2,34.29 167.39,30.48 162.31,30.48 159.77,27.94 R373.1
N$69
  Oben/V2 0.762: V326.1 161.34,33.33 161.04,33.02 R371.1
N$70
  Oben/V2 0.762: V326.4 161.34,35.26 161.04,35.56 R370.1
N$71  (via drill 3.2 pad 5.99)
  other vias: 82.3,128.27
N$72
  Unten/V1 1.016: IC302.7 V328.1
N$73
  Oben/V2 1.524: G325.1 168.66,90.17 168.66,85.34 167.14,83.82 R362.2
  Unten/V1 1.524: R362.2 163.58,81.28 V324.1
N$74
  Oben/V2 1.524: R353.1 R352.1 | R354.1 R353.1 | R355.1 R354.1 | R360.1 R361.1 163.58,86.36 163.58,88.9 | R360.1 R359.1 | R359.1 R358.1 | R358.1 R357.1 | R357.1 R356.1 | R356.1 R355.1 | R352.1 168.66,109.22 169.93,107.95 | R358.1 167.39,93.98 167.39,92.71 R359.1 | 167.39,101.6 167.39,99.06 R356.1 | 167.39,101.6 167.39,104.14 R354.1 | R353.1 169.93,106.68 | R355.1 167.39,101.6 | R357.1 169.93,96.52 | R352.1 163.58,109.22 163.58,106.68 | 163.58,104.14 163.58,106.68 | 163.58,101.6 163.58,104.14 | 163.58,99.06 163.58,101.6 | 163.58,96.52 163.58,99.06 | 163.58,93.98 163.58,96.52 | 163.58,91.44 163.58,93.98 | 163.58,88.9 163.58,91.44 | R360.1 163.58,88.9 | R359.1 163.58,91.44 | R358.1 163.58,93.98 | R357.1 163.58,96.52 | R356.1 163.58,99.06 | R355.1 163.58,101.6 | R354.1 163.58,104.14 | R353.1 163.58,106.68
  Oben/V2 2.54: 169.93,96.52 173.74,96.52
  Oben/V2 2.794: 167.39,93.98 169.93,96.52 167.39,99.06 | 167.39,104.14 169.93,106.68 169.93,107.95
  Unten/V1 1.524: 168.66,88.9 168.66,86.36 | R361.1 168.66,86.36 | R352.1 168.66,109.22 169.93,107.95 | 168.66,104.14 169.93,105.41 169.93,106.68 R353.1 | 168.66,96.52 168.66,99.06 | 167.39,91.44 167.39,93.98 | R354.1 168.66,104.14 | R355.1 167.39,101.6 | R356.1 168.66,99.06 | R357.1 168.66,96.52 | R358.1 167.39,93.98 | R359.1 167.39,91.44 | R360.1 168.66,88.9 | R353.1 R352.1 | R354.1 R353.1 | R355.1 R354.1 | R356.1 R355.1 | R357.1 R356.1 | R358.1 R357.1 | R359.1 R358.1 | R360.1 R359.1 | R360.1 R361.1 | 167.39,101.6 167.39,102.87 168.66,104.14 | 168.66,99.06 167.39,100.33 167.39,101.6 | 168.66,99.06 171.2,99.06 172.47,97.79 172.47,96.52 168.66,96.52 | 167.39,93.98 168.66,95.25 168.66,96.52 | 168.66,88.9 173.74,88.9 | 167.39,91.44 167.39,92.71 168.66,93.98 171.2,93.98 173.74,91.44 | 167.39,93.98 173.74,93.98 | R364.1 R363.2 167.39,68.58 168.66,69.85 168.66,86.36 | R352.1 163.58,109.22 163.58,106.68 | 163.58,104.14 163.58,106.68 | 163.58,101.6 163.58,104.14 | 163.58,99.06 163.58,101.6 | 163.58,96.52 163.58,99.06 | 163.58,93.98 163.58,96.52 | 163.58,91.44 163.58,93.98 | 163.58,88.9 163.58,91.44 | 163.58,88.9 163.58,86.36 R361.1 | R360.1 163.58,88.9 | R359.1 163.58,91.44 | R358.1 163.58,93.98 | R357.1 163.58,96.52 | R356.1 163.58,99.06 | R355.1 163.58,101.6 | R354.1 163.58,104.14 | R353.1 163.58,106.68 | 167.39,91.44 167.39,90.17 168.66,88.9
  Unten/V1 2.794: 169.93,106.68 169.93,107.95 | V321.3 173.74,96.52 172.47,96.52
  Unten/V1 3.302: 168.66,86.36 171.2,86.36 173.74,88.9 173.74,91.44 173.74,93.98 173.74,96.52
N$75
  Oben/V2 0.762: V333.2 122.94,33.02 R397.2
  Unten/V1 1.016: R397.2 126.75,27.94 122.94,31.75 122.94,34.29 121.67,35.56 V337.1
N$76
  Oben/V2 0.762: V333.1 123.24,35.26 122.94,35.56
  Oben/V2 1.016: R393.2 125.48,38.1 122.94,35.56
N$77
  Oben/V2 0.762: V333.3 125.17,33.33 125.48,33.02
  Oben/V2 1.016: 125.48,33.02 R395.1
N$78
  Oben/V2 0.762: V333.4 125.17,35.26 125.48,35.56
  Oben/V2 1.016: 125.48,35.56 R394.1
N$79
  Oben/V2 1.016: R396.1 129.29,30.48 130.56,31.75 130.56,34.29 131.83,35.56 R394.2
  Unten/V1 1.016: V337.3 121.67,40.64 125.48,36.83 125.48,31.75 126.75,30.48 R396.1
N$80
  Oben/V2 1.016: 138.18,68.58 R378.2 | 138.18,68.58 138.18,62.23 139.45,60.96 R381.2 | V337.2 116.59,38.1 112.78,41.91 112.78,46.99 116.59,50.8 V336.1 119.13,50.8 120.4,52.07 120.4,57.15 121.67,58.42 130.56,58.42 | 130.56,58.42 132.34,58.42 135.64,55.12 V329.1 | 130.56,58.42 130.56,64.77 134.37,68.58 138.18,68.58
N$81
  Unten/V1 1.016: R136.1 R137.2 V118.3
N$82
  Oben/V2 1.524: R422.1 R421.1 R420.1 R419.1 R418.1 R417.1 R416.1 R415.1 R414.1 R413.1
  Unten/V1 1.524: R413.1 117.86,109.22 116.59,107.95 | R414.1 116.59,106.68 | R415.1 119.13,104.14 119.13,101.6 | 119.13,91.44 119.13,92.71 117.86,93.98 | 117.86,88.9 119.13,90.17 119.13,91.44 | 117.86,86.36 117.86,88.9 | R418.1 117.86,96.52 | R419.1 117.86,93.98 | 119.13,91.44 R420.1 | 117.86,88.9 R421.1 | 117.86,86.36 R422.1 | R416.1 119.13,101.6 | R417.1 117.86,99.06 | R414.1 R413.1 | R415.1 R414.1 | R416.1 R415.1 | R417.1 R416.1 | R418.1 R417.1 | R419.1 R418.1 | R420.1 R419.1 | R421.1 R420.1 | R422.1 R421.1 | 117.86,99.06 119.13,100.33 119.13,101.6 | 117.86,93.98 117.86,96.52 | 117.86,96.52 117.86,99.06 | 117.86,93.98 115.32,93.98 114.05,92.71 112.78,92.71 | 117.86,88.9 112.78,88.9 | R413.1 122.94,109.22 122.94,106.68 | 122.94,104.14 122.94,106.68 | 122.94,101.6 122.94,104.14 | 122.94,99.06 122.94,101.6 | 122.94,96.52 122.94,99.06 | 122.94,93.98 122.94,96.52 | 122.94,91.44 122.94,93.98 | 122.94,88.9 122.94,91.44 | 122.94,88.9 122.94,86.36 R422.1 | R421.1 122.94,88.9 | R420.1 122.94,91.44 | R419.1 122.94,93.98 | R418.1 122.94,96.52 | R417.1 122.94,99.06 | R416.1 122.94,101.6 | R415.1 122.94,104.14 | R414.1 122.94,106.68 | R425.2 R424.2 119.13,68.58 117.86,69.85 117.86,86.36
  Unten/V1 2.794: 112.78,85.09 112.78,92.71 108.97,92.71 | 105.16,92.71 102.27,95.6 V335.3 102.62,96.52 102.62,90.17 103.89,88.9 112.78,88.9 | 116.59,107.95 116.59,106.68 119.13,104.14 | 108.97,92.71 105.16,92.71 | 117.86,86.36 116.59,85.09 112.78,85.09 | 105.16,85.09 102.62,85.09 101.35,86.36 101.35,96.52 | 108.97,85.09 105.16,85.09 | 112.78,85.09 108.97,85.09 | 108.97,85.09 108.97,92.71 | 105.16,85.09 105.16,92.71
N$83
  Oben/V2 1.524: G330.2 117.86,90.17 117.86,85.34 119.38,83.82 R423.1
  Unten/V1 1.524: R423.1 122.94,81.28 V332.1
N$84
  Oben/V2 1.524: V335.1 112.78,96.52 116.59,100.33 G330.1 116.59,102.87 114.05,105.41 106.43,105.41 102.62,101.6 V334.1 101.35,101.6 98.81,99.06 98.81,95.25 100.08,93.98 100.08,66.04 G333.2
  Unten/V1 1.524: 121.67,53.34 120.4,52.07 120.4,49.53 119.13,48.26 R426.2 | 107.7,58.42 G333.2 | 107.7,58.42 119.13,58.42 120.4,57.15 120.4,54.61 121.67,53.34 | 121.67,53.34 V332.2 | G334.2 107.7,58.42
N$85
  Unten/V1 1.016: J307.1 103.89,5.08 106.43,7.62 122.94,7.62 125.48,10.16 | 125.48,10.16 R402.1 | 125.48,10.16 MP8.1
N$86
  Unten/V1 1.016: V325.3 R363.1
N$87
  Oben/V2 1.016: R368.1 149.61,63.5 147.07,60.96 R381.1
  Unten/V1 1.016: R378.1 150.88,71.12 153.42,68.58 153.42,67.31 152.15,66.04 P301.1 R368.1 153.42,60.96 153.42,57.15 150.88,54.61 V327.3
N$88
  Unten/V1 1.016: R379.2 R380.2 138.18,63.5 | 138.18,63.5 R391.1 135.64,60.96 130.56,55.88 V329.3 | R382.2 139.45,58.42 138.18,59.69 138.18,63.5
N$89  (via drill 0.9 pad 1.5)
  Oben/V2 1.016: 133.1,22.86 V330.2 | R398.2 128.02,24.13 129.29,22.86 133.1,22.86 | IC304.2 133.1,20.32 133.1,22.86 | 110.24,24.13 111.51,25.4 v122.94,25.4 | MP10.1 108.97,25.4 110.24,24.13 | 110.24,24.13 G335.2
  Unten/V1 1.016: v122.94,25.4 R398.2 | V330.2 R392.1
N$90  (via drill 0.9 pad 1.5)
  Oben/V2 1.016: v143.26,48.26 R384.2
  Unten/V1 1.016: 148.34,54.61 R383.2 R384.2 150.88,48.26 153.42,50.8 V327.2 | 148.34,54.61 C321.2 | 148.34,54.61 148.34,55.88 R368.2 | R391.2 133.1,55.88 V329.2 133.1,49.53 136.91,45.72 139.45,45.72 141.99,48.26 v143.26,48.26
N$91
  Oben/V2 1.016: V324.3 163.58,48.26 166.12,45.72 R366.1
  Unten/V1 1.016: V325.1 V324.3 | R366.1 G329.2
N$92
  Unten/V1 1.524: G328.1 R364.2
N$93
  Unten/V1 1.016: R201.1 R200.2 59.44,8.89 58.17,7.62 R189.2
N$94
  Oben/V2 1.016: 126.75,17.78 125.48,19.05 125.48,26.67 124.21,27.94 IC305.1 | R432.2 115.32,11.43 116.59,12.7 121.67,12.7 126.75,17.78 | 126.75,17.78 R400.2
  Unten/V1 1.016: IC305.1 C331.2 | R433.2 R432.2
N$95
  Unten/V1 1.016: IC305.2 117.86,29.21 116.59,30.48 | 116.59,30.48 119.13,33.02 R429.1 | C331.1 116.59,30.48
N$96
  Unten/V1 1.016: IC305.5 G337.2 R433.1
N$97
  Unten/V1 1.016: IC305.6 R432.1 115.32,13.97 117.86,11.43 R431.2 R430.1
N$98
  Unten/V1 1.016: G136.2 83.57,22.86 91.19,15.24 J4.2 105.16,20.32 105.16,21.59 106.43,22.86 G336.2
N$99  (via drill 3.2 pad 5.99)
  other vias: 74.68,247.65
N$100  (via drill 3.2 pad 5.99)
  other vias: 115.32,247.65
N$101
  Oben/V2 1.524: R343.2 R342.2 168.66,134.62 169.93,133.35 | R344.1 R343.2 | R345.2 R344.1 | R346.2 R345.2 | R347.1 R346.2 | R348.1 R347.1 | R349.1 R348.1 | R350.2 R349.1 | R350.2 R351.1 168.66,111.76 169.93,113.03 | R350.2 169.93,114.3 | R349.1 169.93,116.84 | R348.1 169.93,119.38 | R347.1 169.93,121.92 | R346.2 169.93,124.46 | R345.2 169.93,127 | R344.1 169.93,129.54 | R343.2 169.93,132.08
  Oben/V2 2.794: 169.93,113.03 169.93,114.3 169.93,116.84 169.93,119.38 169.93,121.92 169.93,124.46 169.93,127 169.93,129.54 169.93,132.08 169.93,133.35
  Unten/V1 1.524: 173.74,129.54 169.93,133.35 168.66,134.62 R342.2 R343.2 | 173.74,127 173.74,129.54 | 173.74,127 173.74,124.46 169.93,124.46 R346.2 | R343.2 169.93,132.08 | R344.1 169.93,129.54 173.74,129.54 | R345.2 169.93,127 173.74,127 | R347.1 169.93,121.92 173.74,121.92 | R348.1 169.93,119.38 173.74,119.38 | R349.1 169.93,116.84 173.74,116.84 | R350.2 169.93,114.3 173.74,114.3 | 176.28,111.76 171.2,111.76 169.93,111.76 R351.1 R350.2 | R344.1 R343.2 | R345.2 R344.1 | R346.2 R345.2 | R347.1 R346.2 | R348.1 R347.1 | R349.1 R348.1 | R350.2 R349.1
  Unten/V1 2.794: 173.74,119.38 173.74,121.92 173.74,124.46 185.17,113.03 185.17,107.95 | 173.74,119.38 173.74,116.84 173.74,114.3 176.28,111.76 183.9,104.14 | 169.93,133.35 169.93,132.08 169.93,129.54 169.93,127 169.93,124.46 169.93,121.92 169.93,119.38 169.93,116.84 169.93,114.3 169.93,111.76 | 183.9,104.14 183.9,101.95 V320.3 | 185.17,107.95 185.17,102.87 183.9,104.14 | 171.2,111.76 177.55,105.41 181.36,105.41 183.9,102.87 | 173.74,119.38 185.17,107.95
N$102
  Oben/V2 1.524: R404.1 R403.1 117.86,134.62 116.59,133.35 | R404.1 R405.1 | R405.1 R406.2 | R406.2 R407.1 | R407.1 R408.2 | R408.2 R409.1 | R409.1 R410.2 | R410.2 R411.2 | R411.2 R412.2 117.86,111.76 116.59,113.03 | R404.1 116.59,132.08 | R405.1 116.59,129.54 | R406.2 116.59,127 | R407.1 116.59,124.46 | R408.2 116.59,121.92 | R409.1 116.59,119.38 | R410.2 116.59,116.84 | R411.2 116.59,114.3
  Oben/V2 2.794: 116.59,113.03 116.59,114.3 116.59,116.84 116.59,119.38 116.59,121.92 116.59,124.46 116.59,127 116.59,129.54 116.59,132.08 116.59,133.35
  Unten/V1 1.524: 112.78,129.54 112.78,132.08 116.59,132.08 R404.1 | 112.78,129.54 112.78,127 | 112.78,127 112.78,124.46 116.59,124.46 R407.1 | 115.32,111.76 116.59,111.76 R412.2 R411.2 | R411.2 116.59,114.3 112.78,114.3 | R410.2 116.59,116.84 112.78,116.84 | R409.1 116.59,119.38 112.78,119.38 | R408.2 116.59,121.92 112.78,121.92 | R406.2 116.59,127 112.78,127 | R405.1 116.59,129.54 112.78,129.54 | 116.59,133.35 117.86,134.62 R403.1 R404.1 | R404.1 R405.1 | R405.1 R406.2 | R406.2 R407.1 | R407.1 R408.2 | R408.2 R409.1 | R409.1 R410.2 | R410.2 R411.2
  Unten/V1 2.794: 112.78,101.6 112.78,109.22 115.32,111.76 | 116.59,111.76 116.59,114.3 116.59,116.84 116.59,119.38 116.59,121.92 116.59,124.46 116.59,127 116.59,129.54 116.59,132.08 116.59,133.35 114.05,133.35 112.78,132.08 | 112.78,119.38 112.78,121.92 112.78,124.46 107.7,119.38 107.7,114.3 | 112.78,119.38 112.78,116.84 112.78,114.3 110.24,111.76 110.24,105.41 | 110.24,105.41 112.78,102.87 112.78,101.6 | 112.78,101.6 V334.3 | 110.24,105.41 107.7,107.95 107.7,114.3 | 112.78,119.38 107.7,114.3
N$103
  Oben/V2 1.016: C322.1 R385.1 | R429.2 120.4,39.37 124.21,43.18 R428.1 126.75,43.18 131.83,48.26 134.37,48.26 139.45,43.18 C322.1 | R367.2 159.77,43.18 158.5,44.45 158.5,45.72 155.96,48.26 152.15,48.26 149.61,45.72 143.26,45.72 C322.1
  Oben/V2 1.524: 120.4,74.93 G331.2 | 143.26,76.2 143.26,52.07 140.72,49.53 C322.1 | 166.12,74.93 G327.1
  Oben/V2 2.54: T2.12 100.08,157.48 106.43,151.13 106.43,143.51 108.97,140.97 115.32,140.97 117.86,138.43 121.67,138.43 124.21,135.89 124.21,133.35
  Oben/V2 2.794: 177.55,96.52 177.55,100.33 V320.2 180.09,100.33 180.09,96.52 | 177.55,93.98 177.55,96.52 | 175.01,91.44 177.55,93.98 | 169.93,78.74 169.93,74.93 | 169.93,78.74 169.93,82.55 | 169.93,82.55 172.47,85.09 | 175.01,91.44 172.47,88.9 172.47,85.09 | 180.09,83.82 182.63,86.36 182.63,91.44 180.09,93.98 | 177.55,81.28 180.09,83.82 | 172.47,76.2 175.01,78.74 | 175.01,78.74 177.55,81.28 | 169.93,74.93 171.2,74.93 172.47,76.2 | 180.09,93.98 180.09,96.52 | 106.43,96.52 106.43,100.33 V334.2 108.97,100.33 108.97,96.52 | 108.97,93.98 108.97,96.52 | 111.51,91.44 114.05,88.9 114.05,85.09 | 111.51,91.44 108.97,93.98 | 116.59,82.55 116.59,78.74 | 116.59,78.74 116.59,74.93 | 116.59,74.93 115.32,74.93 114.05,76.2 | 111.51,78.74 108.97,81.28 | 108.97,81.28 106.43,83.82 | 106.43,83.82 103.89,86.36 103.89,91.44 106.43,93.98 | 106.43,93.98 106.43,96.52 | 106.43,96.52 107.7,95.25 | J302.1 145.8,74.93 | 135.64,74.93 120.4,74.93 120.4,76.2 | 145.8,74.93 140.72,74.93 | 135.64,74.93 140.72,74.93 | 120.4,76.2 119.13,74.93 116.59,74.93 | 133.1,77.47 145.8,77.47 J302.1 | 133.1,78.74 133.1,77.47 | 116.59,78.74 117.86,77.47 121.67,77.47 122.94,78.74 133.1,78.74 | 169.93,74.93 166.12,74.93 150.88,74.93 | 150.88,74.93 J302.2 152.15,77.47 | 145.8,74.93 150.88,74.93 | 169.93,78.74 168.66,77.47 152.15,77.47 | 153.42,78.74 152.15,77.47 | 153.42,80.01 153.42,78.74 | 153.42,80.01 154.69,81.28 155.96,81.28 157.23,80.01 159.77,80.01 161.04,81.28 163.58,81.28 164.85,80.01 167.39,80.01 169.93,82.55 | 172.47,85.09 172.47,76.2 | 175.01,91.44 175.01,78.74 | 177.55,81.28 177.55,93.98 | 180.09,83.82 180.09,93.98 | 133.1,80.01 131.83,81.28 130.56,81.28 129.29,80.01 126.75,80.01 125.48,81.28 124.21,81.28 122.94,81.28 121.67,80.01 119.13,80.01 116.59,82.55
  Oben/V2 2.794: 133.1,80.01 133.1,78.74 | 116.59,82.55 114.05,85.09 | 114.05,85.09 114.05,76.2 | 114.05,76.2 111.51,78.74 | 111.51,78.74 111.51,91.44 | 108.97,93.98 108.97,81.28 | 106.43,83.82 106.43,93.98 | 133.1,77.47 152.15,77.47 | 180.09,96.52 V321.2 177.55,96.52 | 108.97,96.52 V335.2 106.43,96.52 | 153.42,78.74 169.93,78.74 | J302.1 143.26,76.2 J304.2 | J304.1 J304.2 | 120.4,76.2 J304.1 | J304.1 135.64,74.93 | J304.2 140.72,74.93 | 133.1,80.01 153.42,80.01
  Oben/V2 3.302: 124.21,133.35 124.21,81.28
  Unten/V1 1.016: R388.2 C324.2 139.45,30.48 138.18,31.75 138.18,34.29 139.45,35.56 R386.2 R385.1
  Unten/V1 2.794: 106.43,97.79 106.43,100.33 V334.2 108.97,100.33 108.97,97.79 V335.2 106.43,97.79 | V321.2 177.55,97.79 177.55,100.33 V320.2 180.09,100.33 180.09,97.79 V321.2
N$104
  Oben/V2 1.016: 91.19,182.88 91.19,181.86 92.46,180.59 92.46,106.68 93.73,105.41 93.73,99.06 92.46,97.79 92.46,57.15 93.73,55.88 93.73,33.02 92.46,31.75 R234.2 | J105.1 91.19,182.88 | 91.19,182.88 C132.1
  Unten/V1 1.016: C132.1 91.19,182.88 91.19,184.15 G123.1
N$105
  Oben/V2 1.524: G301.1 167.39,190.5 R313.2
N$106
  Oben/V2 1.016: R309.2 173.74,154.94 G306.1
N$107
  Oben/V2 1.524: 183.9,96.52 187.71,100.33 187.71,104.14 186.44,105.41 177.55,105.41 173.74,101.6 V320.1 G325.2 | 183.9,96.52 V321.1 | 183.9,96.52 186.44,93.98 186.44,66.04 G326.1 | V324.2 164.85,53.34 166.12,52.07 166.12,49.53 167.39,48.26 R365.1
  Unten/V1 1.524: G326.1 176.28,55.88 176.28,48.26 | 176.28,48.26 R365.1 | 176.28,48.26 G329.1
N$108
  Oben/V2 1.016: C326.1 148.34,10.16 C320.1
  Unten/V1 1.016: R402.2 C326.1
N$109
  Oben/V2 1.016: R308.1 177.55,162.56 176.28,161.29 176.28,160.02 R310.2 | C303.2 168.66,160.02 R317.2
  Unten/V1 1.016: 171.2,157.48 171.2,153.67 167.39,149.86 G308.2 | 171.2,157.48 168.66,160.02 C303.2 | 171.2,157.48 R310.2
N$110
  Oben/V2 1.016: V309.2 175.01,167.64 176.28,166.37 176.28,163.83 175.01,162.56 R308.2 172.47,162.56 171.2,161.29 171.2,158.75 169.93,157.48 166.12,157.48 | 166.12,157.48 C307.1 | R318.1 166.12,157.48
N$111
  Oben/V2 1.016: G302.2 162.31,193.04 V305.1 161.04,186.69 162.31,185.42 G304.2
